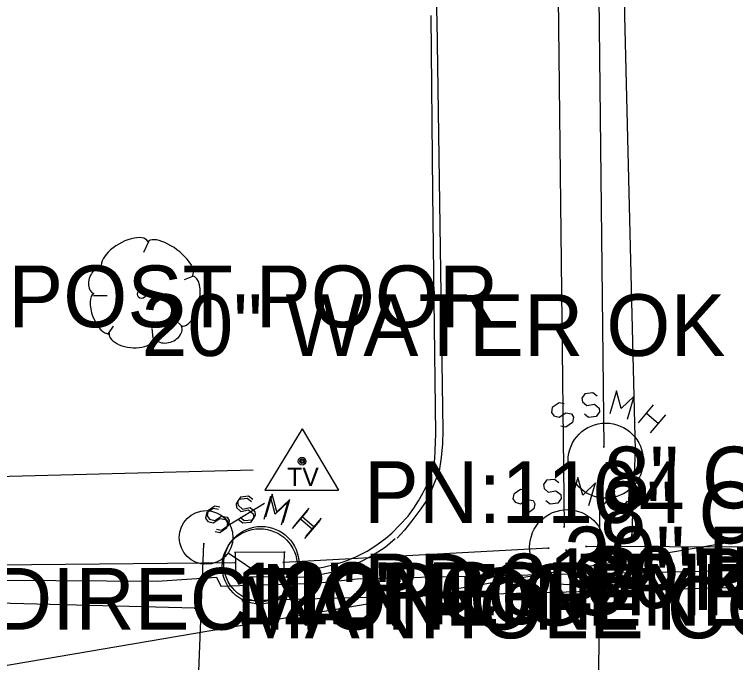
# Model space of a CAD drawing. Extents: x 1304270 to 1306561, y 1876019 to 1876752.
# Drawn here: x 1306184.9 to 1306243.3, y 1876424.3 to 1876476.9 of the extents above; entities that cross this region are included whole.
import ezdxf

# ---------------------------------------------------------------- set-up
doc = ezdxf.new("R2010")
doc.units = 0
for name, color, linetype in [('Default', 7, 'Continuous'), ('S_CURB', 7, 'Continuous'), ('S_DRG_PT_SYM', 7, 'Continuous'), ('S_EDGE_CONCRETE', 7, 'Continuous'), ('S_EDGE_PAVEMENT', 7, 'Continuous'), ('S_FENCE_ANNOT', 7, 'Continuous'), ('S_MANHOLE', 7, 'Continuous'), ('S_MANHOLE_ANNOT', 7, 'Continuous'), ('S_MISC_STRUCTURES', 7, 'Continuous'), ('S_MISC_STRUCTURES_ANNOT', 7, 'Continuous'), ('S_MSC_PT_SYM', 7, 'Continuous'), ('S_PAVEMENT_CROWN', 7, 'Continuous'), ('S_SANITARY_SEWER', 7, 'Continuous'), ('S_SANITARY_SEWER_ANNOT', 7, 'Continuous'), ('S_SECONDARY_CTL', 7, 'Continuous'), ('S_SECONDARY_CTL_ANNOT', 7, 'Continuous'), ('S_STORM_SEWER', 7, 'Continuous'), ('S_STORM_SEWER_ANNOT', 7, 'Continuous'), ('S_TRAILS', 7, 'Continuous'), ('S_TREE', 7, 'Continuous'), ('S_TREE_ANNOT', 7, 'Continuous'), ('S_UTL_PT_SYM', 7, 'Continuous'), ('S_WATER_UTILITIES', 7, 'Continuous')]:
    doc.layers.add(name, color=color, linetype=linetype)

msp = doc.modelspace()

# ---------------------------------------------------------------- linework, layer by layer
at = {"layer": 'Default'}
msp.add_line((1305993.253, 1876391.553), (1306312.09, 1876445.884), dxfattribs=at)
at = {"layer": 'S_CURB'}
msp.add_lwpolyline([(1306206.857, 1876431.75), (1306208.677, 1876431.864), (1306209.88, 1876432.051), (1306210.985, 1876432.33), (1306211.745, 1876432.565), (1306212.538, 1876432.899), (1306213.459, 1876433.362), (1306214.155, 1876433.806), (1306214.927, 1876434.378), (1306215.436, 1876434.802), (1306216.098, 1876435.481), (1306216.773, 1876436.184), (1306217.223, 1876436.844), (1306217.603, 1876437.429), (1306217.969, 1876438.062), (1306218.276, 1876438.697), (1306218.577, 1876439.407), (1306218.754, 1876439.914), (1306218.846, 1876440.397), (1306218.927, 1876440.811), (1306218.953, 1876441.503), (1306219.008, 1876442.873), (1306218.761, 1876462.408), (1306218.637, 1876476.782)], dxfattribs=at)
at = {"layer": 'S_DRG_PT_SYM'}
msp.add_lwpolyline([(1306204.775, 1876431.056), (1306204.775, 1876431.106), (1306204.775, 1876431.056), (1306204.725, 1876431.056), (1306204.775, 1876431.056), (1306204.775, 1876431.006), (1306204.775, 1876431.056), (1306204.825, 1876431.056)], dxfattribs=at)
at = {"layer": 'S_EDGE_CONCRETE'}
msp.add_lwpolyline([(1306215.708, 1876434.343), (1306214.899, 1876433.65), (1306213.79, 1876432.936), (1306212.863, 1876432.465), (1306211.257, 1876431.76), (1306210.282, 1876431.573), (1306208.992, 1876431.304), (1306207.984, 1876431.211), (1306206.762, 1876431.234)], dxfattribs=at)
at = {"layer": 'S_EDGE_PAVEMENT'}
for points in [[(1306218.613, 1876518.304), (1306218.815, 1876499.726), (1306218.673, 1876488.347), (1306219.095, 1876476.375), (1306219.343, 1876459.757), (1306219.591, 1876443.139), (1306219.567, 1876442.038), (1306219.458, 1876440.95), (1306219.294, 1876439.841), (1306218.914, 1876438.908), (1306218.403, 1876437.649), (1306217.811, 1876436.787), (1306217.079, 1876435.809), (1306216.471, 1876435.049), (1306215.881, 1876434.409)], [(1306113.118, 1876430.252), (1306126.16, 1876430.644), (1306148.959, 1876430.86), (1306171.757, 1876431.076), (1306196.43, 1876430.925), (1306201.225, 1876431.253), (1306201.586, 1876430.503), (1306204.639, 1876430.618), (1306209.255, 1876430.767), (1306212.625, 1876431.106), (1306218.847, 1876431.256), (1306235.37, 1876431.614), (1306256.719, 1876432.089), (1306262.367, 1876432.425), (1306275.555, 1876432.506), (1306288.743, 1876432.587), (1306294.654, 1876432.627), (1306294.992, 1876432.685), (1306300.36, 1876432.776), (1306312.863, 1876432.808), (1306325.367, 1876432.841), (1306326.28, 1876432.716), (1306334.347, 1876433.018), (1306341.345, 1876433.309)]]:
    msp.add_lwpolyline(points, dxfattribs=at)
at = {"layer": 'S_MANHOLE'}
for p, q in [((1306200.961, 1876436.809), (1306200.418, 1876436.422)), ((1306201.088, 1876436.998), (1306200.545, 1876436.611)), ((1306201.387, 1876436.732), (1306200.961, 1876436.809)), ((1306201.514, 1876436.921), (1306201.088, 1876436.998)), ((1306207.52, 1876435.371), (1306208.76, 1876436.843)), ((1306200.418, 1876436.422), (1306200.341, 1876436.034)), ((1306200.545, 1876436.611), (1306200.468, 1876436.223)), ((1306200.468, 1876436.223), (1306200.661, 1876435.952)), ((1306207.393, 1876435.182), (1306208.633, 1876436.654)), ((1306200.341, 1876436.034), (1306200.534, 1876435.763)), ((1306200.534, 1876435.763), (1306200.961, 1876435.647)), ((1306200.661, 1876435.952), (1306201.088, 1876435.836)), ((1306200.961, 1876435.647), (1306201.503, 1876435.996)), ((1306201.088, 1876435.836), (1306201.63, 1876436.185)), ((1306201.503, 1876435.996), (1306201.968, 1876435.918)), ((1306201.63, 1876436.185), (1306202.095, 1876436.107)), ((1306201.968, 1876435.918), (1306202.123, 1876435.647)), ((1306202.123, 1876435.647), (1306202.046, 1876435.221)), ((1306202.095, 1876436.107), (1306202.25, 1876435.836)), ((1306202.25, 1876435.836), (1306202.173, 1876435.41)), ((1306208.052, 1876435.957), (1306209.021, 1876435.143)), ((1306208.179, 1876436.146), (1306209.148, 1876435.332)), ((1306209.602, 1876435.841), (1306208.362, 1876434.368)), ((1306209.729, 1876436.03), (1306208.489, 1876434.557)), ((1306201.63, 1876435.022), (1306201.243, 1876435.1)), ((1306202.046, 1876435.221), (1306201.503, 1876434.833)), ((1306202.173, 1876435.41), (1306201.63, 1876435.022)), ((1306201.503, 1876434.833), (1306201.116, 1876434.911))]:
    msp.add_line(p, q, dxfattribs=at)
for points in [[(1306206.629, 1876435.681), (1306207.171, 1876437.541), (1306206.125, 1876436.533), (1306205.738, 1876437.967), (1306205.195, 1876436.107)], [(1306204.061, 1876437.352), (1306203.712, 1876437.623), (1306203.053, 1876437.546), (1306202.821, 1876437.197), (1306202.859, 1876436.887), (1306203.208, 1876436.577), (1306203.828, 1876436.693), (1306204.216, 1876436.383), (1306204.254, 1876436.073), (1306203.983, 1876435.686), (1306203.363, 1876435.608), (1306203.014, 1876435.879)], [(1306204.188, 1876437.541), (1306203.839, 1876437.812), (1306203.18, 1876437.735), (1306202.948, 1876437.386), (1306202.986, 1876437.076), (1306203.335, 1876436.766), (1306203.955, 1876436.882), (1306204.343, 1876436.572), (1306204.381, 1876436.262), (1306204.11, 1876435.875), (1306203.49, 1876435.797), (1306203.141, 1876436.068)], [(1306206.502, 1876435.492), (1306207.044, 1876437.352), (1306205.998, 1876436.344), (1306205.611, 1876437.778), (1306205.068, 1876435.918)]]:
    msp.add_lwpolyline(points, dxfattribs=at)
for centre in [(1306204.745, 1876432.119), (1306204.872, 1876432.308)]:
    msp.add_circle(centre, 3.048, dxfattribs=at)
at = {"layer": 'S_MISC_STRUCTURES'}
for p, q in [((1306206.752, 1876433.268), (1306202.75, 1876433.234)), ((1306202.75, 1876433.234), (1306202.816, 1876431.284)), ((1306206.697, 1876431.254), (1306206.752, 1876433.268)), ((1306202.816, 1876431.284), (1306206.697, 1876431.254))]:
    msp.add_line(p, q, dxfattribs=at)
at = {"layer": 'S_MSC_PT_SYM'}
for points in [[(1306206.752, 1876433.268), (1306206.752, 1876433.318), (1306206.752, 1876433.268), (1306206.702, 1876433.268), (1306206.752, 1876433.268), (1306206.752, 1876433.218), (1306206.752, 1876433.268), (1306206.802, 1876433.268)], [(1306202.75, 1876433.234), (1306202.75, 1876433.284), (1306202.75, 1876433.234), (1306202.7, 1876433.234), (1306202.75, 1876433.234), (1306202.75, 1876433.184), (1306202.75, 1876433.234), (1306202.8, 1876433.234)], [(1306202.816, 1876431.284), (1306202.816, 1876431.334), (1306202.816, 1876431.284), (1306202.766, 1876431.284), (1306202.816, 1876431.284), (1306202.816, 1876431.234), (1306202.816, 1876431.284), (1306202.866, 1876431.284)], [(1306206.697, 1876431.254), (1306206.697, 1876431.304), (1306206.697, 1876431.254), (1306206.647, 1876431.254), (1306206.697, 1876431.254), (1306206.697, 1876431.204), (1306206.697, 1876431.254), (1306206.747, 1876431.254)]]:
    msp.add_lwpolyline(points, dxfattribs=at)
at = {"layer": 'S_PAVEMENT_CROWN'}
msp.add_lwpolyline([(1306234.388, 1876518.594), (1306234.152, 1876506.545), (1306234.488, 1876504.577), (1306234.64, 1876503.04), (1306234.47, 1876489.897), (1306234.3, 1876476.755), (1306234.741, 1876459.131), (1306235.181, 1876441.507), (1306234.88, 1876434.411)], dxfattribs=at)
at = {"layer": 'S_SANITARY_SEWER'}
for p, q in [((1306230.819, 1876604.437), (1306232.633, 1876441.82)), ((1306228.456, 1876444.991), (1306228.379, 1876444.603)), ((1306228.999, 1876445.378), (1306228.456, 1876444.991)), ((1306229.425, 1876445.301), (1306228.999, 1876445.378)), ((1306235.431, 1876443.751), (1306236.671, 1876445.223)), ((1306228.379, 1876444.603), (1306228.573, 1876444.332)), ((1306228.999, 1876444.216), (1306229.541, 1876444.564)), ((1306229.541, 1876444.564), (1306230.006, 1876444.487)), ((1306230.006, 1876444.487), (1306230.161, 1876444.216)), ((1306236.09, 1876444.526), (1306237.059, 1876443.712)), ((1306237.64, 1876444.409), (1306236.4, 1876442.937)), ((1306228.573, 1876444.332), (1306228.999, 1876444.216)), ((1306230.161, 1876444.216), (1306230.084, 1876443.789)), ((1306229.541, 1876443.402), (1306229.154, 1876443.479)), ((1306230.084, 1876443.789), (1306229.541, 1876443.402)), ((1306232.192, 1876417.716), (1306232.346, 1876438.98)), ((1306225.341, 1876437.97), (1306225.264, 1876437.583)), ((1306225.884, 1876438.358), (1306225.341, 1876437.97)), ((1306226.31, 1876438.28), (1306225.884, 1876438.358)), ((1306232.316, 1876436.73), (1306233.556, 1876438.203)), ((1306225.264, 1876437.583), (1306225.458, 1876437.311)), ((1306225.884, 1876437.195), (1306226.426, 1876437.544)), ((1306226.426, 1876437.544), (1306226.891, 1876437.466)), ((1306226.891, 1876437.466), (1306227.046, 1876437.195)), ((1306232.975, 1876437.505), (1306233.944, 1876436.691)), ((1306234.525, 1876437.389), (1306233.285, 1876435.916)), ((1306225.458, 1876437.311), (1306225.884, 1876437.195)), ((1306227.046, 1876437.195), (1306226.969, 1876436.769)), ((1306226.426, 1876436.381), (1306226.039, 1876436.459)), ((1306226.969, 1876436.769), (1306226.426, 1876436.381))]:
    msp.add_line(p, q, dxfattribs=at)
for points in [[(1306232.099, 1876445.921), (1306231.75, 1876446.192), (1306231.091, 1876446.114), (1306230.859, 1876445.766), (1306230.898, 1876445.456), (1306231.246, 1876445.146), (1306231.866, 1876445.262), (1306232.254, 1876444.952), (1306232.293, 1876444.642), (1306232.021, 1876444.254), (1306231.401, 1876444.177), (1306231.053, 1876444.448)], [(1306234.54, 1876444.061), (1306235.083, 1876445.921), (1306234.036, 1876444.913), (1306233.649, 1876446.347), (1306233.106, 1876444.487)], [(1306228.984, 1876438.9), (1306228.635, 1876439.171), (1306227.976, 1876439.094), (1306227.744, 1876438.745), (1306227.783, 1876438.435), (1306228.131, 1876438.125), (1306228.751, 1876438.241), (1306229.139, 1876437.931), (1306229.178, 1876437.621), (1306228.906, 1876437.234), (1306228.286, 1876437.156), (1306227.938, 1876437.428)], [(1306231.425, 1876437.04), (1306231.968, 1876438.9), (1306230.921, 1876437.893), (1306230.534, 1876439.326), (1306229.991, 1876437.466)]]:
    msp.add_lwpolyline(points, dxfattribs=at)
for centre in [(1306232.783, 1876440.687), (1306229.668, 1876433.667)]:
    msp.add_circle(centre, 3.048, dxfattribs=at)
at = {"layer": 'S_SECONDARY_CTL'}
for p, q in [((1306208.173, 1876443.254), (1306205.163, 1876438.3)), ((1306208.173, 1876443.254), (1306211.12, 1876438.3)), ((1306205.163, 1876438.3), (1306211.12, 1876438.3))]:
    msp.add_line(p, q, dxfattribs=at)
for radius in [0.311, 0.183, 0.103]:
    msp.add_circle((1306208.173, 1876440.644), radius, dxfattribs=at)
at = {"layer": 'S_STORM_SEWER'}
for p, q in [((1306228.792, 1876491.508), (1306229.409, 1876435.331)), ((1306228.143, 1876433.584), (1306206.654, 1876432.432)), ((1306287.103, 1876433.491), (1306231.2, 1876433.733)), ((1306155.445, 1876431.985), (1306202.78, 1876432.425))]:
    msp.add_line(p, q, dxfattribs=at)
at = {"layer": 'S_TRAILS'}
msp.add_lwpolyline([(1306125.179, 1876437.882), (1306204.201, 1876439.951)], dxfattribs=at)
at = {"layer": 'S_TREE'}
for p, q in [((1306195.718, 1876458.421), (1306195.331, 1876457.569)), ((1306191.921, 1876456.406), (1306192.424, 1876455.825)), ((1306199.283, 1876455.631), (1306198.624, 1876455.36)), ((1306191.262, 1876454.081), (1306192.386, 1876454.081)), ((1306192.424, 1876450.904), (1306192.889, 1876451.601)), ((1306198.508, 1876451.524), (1306198.043, 1876451.95)), ((1306196.106, 1876450.632), (1306196.028, 1876451.407))]:
    msp.add_line(p, q, dxfattribs=at)
msp.add_circle((1306195.16, 1876454.176), 0.341, dxfattribs=at)
for centre, major_axis, ratio, start_param, end_param in [((1306193.824, 1876457.378), (1.857, 1.085), 0.471018, 0, 3.141593), ((1306197.479, 1876457.055), (-1.813, 1.36), 0.405113, 3.141593, 6.283186), ((1306191.589, 1876455.263), (0.305, 1.027), 0.646762, 0, 3.141593), ((1306198.834, 1876453.646), (0.458, 2.04), 0.482994, 3.141593, 6.283185), ((1306191.895, 1876452.613), (-0.611, 1.596), 0.420543, 6.283185, 9.424777), ((1306197.312, 1876451.125), (1.092, 0.462), 0.711534, 3.141592, 6.283185), ((1306194.355, 1876450.832), (-1.832, 0.194), 0.529943, 0, 3.141593)]:
    msp.add_ellipse(centre, major_axis=major_axis, ratio=ratio, start_param=start_param, end_param=end_param, dxfattribs=at)
at = {"layer": 'S_UTL_PT_SYM'}
for points in [[(1306232.633, 1876441.82), (1306232.633, 1876441.87), (1306232.633, 1876441.82), (1306232.583, 1876441.82), (1306232.633, 1876441.82), (1306232.633, 1876441.77), (1306232.633, 1876441.82), (1306232.683, 1876441.82)], [(1306232.843, 1876440.515), (1306232.843, 1876440.565), (1306232.843, 1876440.515), (1306232.793, 1876440.515), (1306232.843, 1876440.515), (1306232.843, 1876440.465), (1306232.843, 1876440.515), (1306232.893, 1876440.515)], [(1306232.346, 1876438.98), (1306232.346, 1876439.03), (1306232.346, 1876438.98), (1306232.296, 1876438.98), (1306232.346, 1876438.98), (1306232.346, 1876438.93), (1306232.346, 1876438.98), (1306232.396, 1876438.98)], [(1306229.409, 1876435.331), (1306229.409, 1876435.381), (1306229.409, 1876435.331), (1306229.359, 1876435.331), (1306229.409, 1876435.331), (1306229.409, 1876435.281), (1306229.409, 1876435.331), (1306229.459, 1876435.331)], [(1306200.217, 1876433.944), (1306200.217, 1876433.994), (1306200.217, 1876433.944), (1306200.167, 1876433.944), (1306200.217, 1876433.944), (1306200.217, 1876433.894), (1306200.217, 1876433.944), (1306200.267, 1876433.944)], [(1306228.143, 1876433.584), (1306228.143, 1876433.634), (1306228.143, 1876433.584), (1306228.093, 1876433.584), (1306228.143, 1876433.584), (1306228.143, 1876433.534), (1306228.143, 1876433.584), (1306228.193, 1876433.584)], [(1306229.589, 1876433.428), (1306229.589, 1876433.478), (1306229.589, 1876433.428), (1306229.539, 1876433.428), (1306229.589, 1876433.428), (1306229.589, 1876433.378), (1306229.589, 1876433.428), (1306229.639, 1876433.428)], [(1306231.2, 1876433.733), (1306231.2, 1876433.783), (1306231.2, 1876433.733), (1306231.15, 1876433.733), (1306231.2, 1876433.733), (1306231.2, 1876433.683), (1306231.2, 1876433.733), (1306231.25, 1876433.733)], [(1306202.78, 1876432.425), (1306202.78, 1876432.475), (1306202.78, 1876432.425), (1306202.73, 1876432.425), (1306202.78, 1876432.425), (1306202.78, 1876432.375), (1306202.78, 1876432.425), (1306202.83, 1876432.425)], [(1306204.454, 1876432.178), (1306204.454, 1876432.228), (1306204.454, 1876432.178), (1306204.404, 1876432.178), (1306204.454, 1876432.178), (1306204.454, 1876432.128), (1306204.454, 1876432.178), (1306204.504, 1876432.178)], [(1306206.654, 1876432.432), (1306206.654, 1876432.482), (1306206.654, 1876432.432), (1306206.604, 1876432.432), (1306206.654, 1876432.432), (1306206.654, 1876432.382), (1306206.654, 1876432.432), (1306206.704, 1876432.432)], [(1306206.697, 1876432.425), (1306206.697, 1876432.475), (1306206.697, 1876432.425), (1306206.647, 1876432.425), (1306206.697, 1876432.425), (1306206.697, 1876432.375), (1306206.697, 1876432.425), (1306206.747, 1876432.425)], [(1306203.334, 1876429.328), (1306203.334, 1876429.378), (1306203.334, 1876429.328), (1306203.284, 1876429.328), (1306203.334, 1876429.328), (1306203.334, 1876429.278), (1306203.334, 1876429.328), (1306203.384, 1876429.328)], [(1306199.481, 1876428.718), (1306199.481, 1876428.768), (1306199.481, 1876428.718), (1306199.431, 1876428.718), (1306199.481, 1876428.718), (1306199.481, 1876428.667), (1306199.481, 1876428.718), (1306199.532, 1876428.718)]]:
    msp.add_lwpolyline(points, dxfattribs=at)
at = {"layer": 'S_WATER_UTILITIES'}
for p, q in [((1306202.298, 1876435.516), (1306205.121, 1876437.248)), ((1306198.596, 1876394.198), (1306200.217, 1876433.944)), ((1306202.174, 1876433.207), (1306205.082, 1876431.28)), ((1306264.575, 1876430.964), (1306203.334, 1876429.328)), ((1306199.481, 1876428.718), (1306161.443, 1876429.715))]:
    msp.add_line(p, q, dxfattribs=at)
msp.add_circle((1306200.394, 1876434.461), 2.177, dxfattribs=at)

# ---------------------------------------------------------------- texts
at = {"layer": 'S_FENCE_ANNOT'}
msp.add_text("4' CHAINLINK MTL POST POOR", height=5, dxfattribs=at).set_placement((1306124.743, 1876451.51))
at = {"layer": 'S_MANHOLE_ANNOT'}
msp.add_text('NONE GENERIC LID', height=5, dxfattribs=at).set_placement((1306204.872, 1876427.308))
at = {"layer": 'S_MISC_STRUCTURES_ANNOT'}
msp.add_text('MANHOLE COVER', height=5, dxfattribs=at).set_placement((1306202.816, 1876426.284))
at = {"layer": 'S_SANITARY_SEWER_ANNOT'}
for s, p in [('8" CLAY', (1306232.633, 1876436.82)), ('8" CMP', (1306232.346, 1876433.98))]:
    msp.add_text(s, height=5, dxfattribs=at).set_placement(p)
at = {"layer": 'S_SECONDARY_CTL'}
msp.add_text('TV', height=1.5, rotation=360, dxfattribs=at).set_placement((1306206.968, 1876438.632))
at = {"layer": 'S_SECONDARY_CTL_ANNOT'}
for s, p in [('PN:1104', (1306213.173, 1876435.644)), ('PD:8 SPIKE', (1306213.173, 1876428.144))]:
    msp.add_text(s, height=5, dxfattribs=at).set_placement(p)
at = {"layer": 'S_STORM_SEWER_ANNOT'}
for s, p in [('30" RCP', (1306229.409, 1876430.331)), ('12" RCP', (1306228.143, 1876428.584)), ('30" RCP', (1306231.2, 1876428.733)), ('12" RCP', (1306202.78, 1876427.425)), ('12" RCP', (1306206.654, 1876427.432)), ('12" RCP', (1306206.697, 1876427.425)), ('12" RCP DIRECTION ONLY', (1306155.445, 1876426.985))]:
    msp.add_text(s, height=5, dxfattribs=at).set_placement(p)
at = {"layer": 'S_TREE_ANNOT'}
msp.add_text('20" WATER OK', height=5, dxfattribs=at).set_placement((1306195.16, 1876449.176))

doc.saveas('drawing.dxf')
